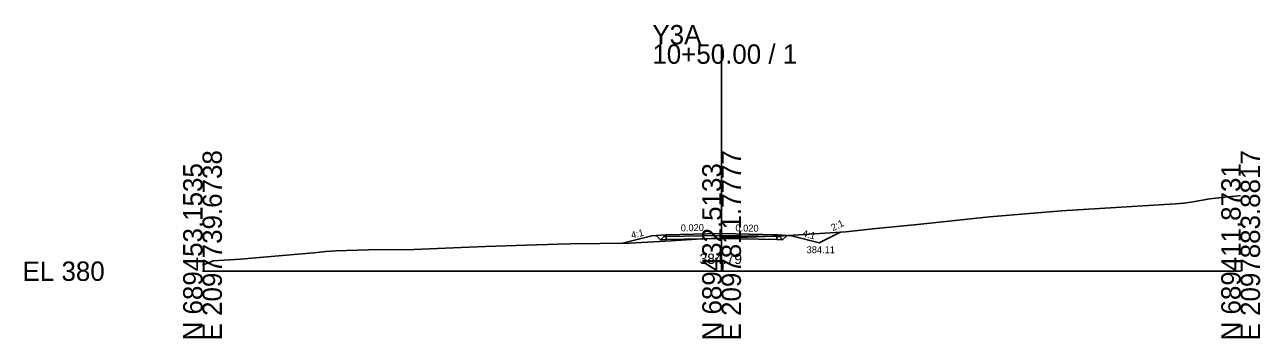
# Model space of a CAD drawing. Extents: x -26 to 2453, y -10 to 1032.
# Drawn here: x -25.7 to 152.8, y 490.3 to 535.6 of the extents above; entities that cross this region are included whole.
import ezdxf

# ---------------------------------------------------------------- set-up
doc = ezdxf.new("R2010")
doc.units = 0
for name, color, linetype in [('Exist Cross Section Cell', 7, 'Continuous'), ('Exist XS Center Line Elevation Label', 7, 'Continuous'), ('Exist XS Ground Line', 7, 'Continuous'), ('Prop CMT Pvmt Course 1', 7, 'Continuous'), ('Prop CMT Pvmt Course 2', 7, 'Continuous'), ('Prop CMT Pvmt Course 3', 7, 'Continuous'), ('Prop CMT Pvmt Surface', 7, 'Continuous'), ('Prop CMT Pvmt Surface Shoulder', 7, 'Continuous'), ('Prop CMT Shld Paved Course 1', 7, 'Continuous'), ('Prop CMT Shld Paved Course 2', 7, 'Continuous'), ('Prop CMT Shld Paved Course 3', 7, 'Continuous'), ('Prop CMT Slope Grass', 7, 'Continuous'), ('Prop CMT Subgrade Earthwork', 7, 'Continuous'), ('Prop XS SE Text', 7, 'Continuous'), ('Prop XS Side Slope Text', 7, 'Continuous')]:
    doc.layers.add(name, color=color, linetype=linetype)

msp = doc.modelspace()

# ---------------------------------------------------------------- linework, layer by layer
at = {"layer": 'Exist Cross Section Cell'}
for p, q in [((75, 500), (75, 532.77)), ((0, 500), (75, 500)), ((75, 500), (150, 500))]:
    msp.add_line(p, q, dxfattribs=at)
at = {"layer": 'Exist XS Ground Line'}
msp.add_lwpolyline([(0, 500.87), (1.56, 501.49), (5.49, 501.73), (11.57, 502.25), (16.06, 502.66), (17.84, 502.83), (19.29, 502.93), (23.98, 503.07), (30.51, 503.12), (38.55, 503.47), (40.91, 503.55), (46.8, 503.77), (51.32, 503.9), (53.13, 503.94), (61.72, 504.07), (67.7, 504.41), (72.12, 504.7), (75, 504.79), (82.52, 505.05), (83.14, 505.08), (92.93, 505.69), (96.85, 506.1), (103.33, 506.73), (111.43, 507.62), (113.73, 507.86), (119.48, 508.35), (124.14, 508.73), (140.6, 509.73), (141.74, 509.81), (142.84, 509.99), (145.53, 510.44), (148.6, 510.78), (148.92, 510.81), (150, 510.92)], dxfattribs=at)
at = {"layer": 'Prop CMT Pvmt Course 1'}
for points in [[(75, 505.43), (67, 505.27)], [(67, 505.27), (67, 505.02)], [(75, 505.18), (75, 505.43)], [(75, 505.43), (83, 505.27)], [(75, 505.18), (75, 505.43)], [(75, 505.18), (75, 505.43)], [(83, 505.27), (83, 505.02)], [(67, 505.02), (75, 505.18)], [(83, 505.02), (75, 505.18)]]:
    msp.add_lwpolyline(points, dxfattribs=at)
msp.add_lwpolyline([(75, 505.18), (75, 505.31), (75, 505.31), (75, 505.18)], close=True, dxfattribs=at)
msp.add_lwpolyline([(75, 505.18), (75, 505.31), (75, 505.31), (75, 505.18)], close=True, dxfattribs=at)
msp.add_lwpolyline([(75, 505.18), (75, 505.31), (75, 505.31), (75, 505.18)], close=True, dxfattribs=at)
msp.add_lwpolyline([(75, 505.18), (75, 505.31), (75, 505.31), (75, 505.18)], close=True, dxfattribs=at)
at = {"layer": 'Prop CMT Pvmt Course 2'}
for points in [[(67, 505.02), (75, 505.18)], [(75, 505.18), (67, 505.02)], [(67, 505.02), (67, 504.69)], [(75, 504.85), (75, 505.18)], [(83, 505.02), (75, 505.18)], [(75, 504.85), (75, 505.18)], [(75, 505.18), (83, 505.02)], [(75, 504.85), (75, 505.18)], [(83, 505.02), (83, 504.69)]]:
    msp.add_lwpolyline(points, dxfattribs=at)
at = {"layer": 'Prop CMT Pvmt Course 3'}
for points in [[(75, 505.18), (67, 505.02)], [(67, 505.02), (67, 504.56)], [(67, 504.56), (75, 504.72)], [(75, 505.18), (83, 505.02)], [(75, 504.72), (75, 505.18)], [(75, 504.72), (75, 505.18)], [(83, 504.56), (75, 504.72)], [(83, 505.02), (83, 504.56)]]:
    msp.add_lwpolyline(points, dxfattribs=at)
at = {"layer": 'Prop CMT Pvmt Surface'}
for points in [[(75, 505.43), (67, 505.27)], [(75, 505.43), (83, 505.27)]]:
    msp.add_lwpolyline(points, dxfattribs=at)
at = {"layer": 'Prop CMT Pvmt Surface Shoulder'}
for points in [[(67, 505.27), (66.9, 505.27)], [(83, 505.27), (83.1, 505.27)]]:
    msp.add_lwpolyline(points, dxfattribs=at)
at = {"layer": 'Prop CMT Shld Paved Course 1'}
for points in [[(67, 505.27), (66.9, 505.27), (66.64, 505.01)], [(67, 505.02), (67, 505.27)], [(83, 505.27), (83.1, 505.27), (83.36, 505.01)], [(83, 505.02), (83, 505.27)], [(66.64, 505.01), (67, 505.02)], [(83.36, 505.01), (83, 505.02)]]:
    msp.add_lwpolyline(points, dxfattribs=at)
at = {"layer": 'Prop CMT Shld Paved Course 2'}
for points in [[(67, 505.02), (66.64, 505.01), (66.31, 504.68)], [(66.64, 505.01), (67, 505.02)], [(67, 504.69), (67, 505.02)], [(83, 505.02), (83.36, 505.01), (83.69, 504.68)], [(83.36, 505.01), (83, 505.02)], [(83, 504.69), (83, 505.02)]]:
    msp.add_lwpolyline(points, dxfattribs=at)
at = {"layer": 'Prop CMT Shld Paved Course 3'}
for points in [[(66.64, 505.01), (66.18, 504.55)], [(66.18, 504.55), (67, 504.56)], [(66.31, 504.68), (66.31, 504.68)], [(67, 505.02), (66.64, 505.01)], [(67, 504.56), (67, 505.02)], [(83, 505.02), (83.36, 505.01)], [(83, 504.56), (83, 505.02)], [(83.82, 504.55), (83, 504.56)], [(83.36, 505.01), (83.82, 504.55)], [(83.69, 504.68), (83.69, 504.68)]]:
    msp.add_lwpolyline(points, dxfattribs=at)
at = {"layer": 'Prop CMT Slope Grass'}
for p, q in [((66.9, 505.27), (64.91, 505.11)), ((83.1, 505.27), (85.09, 505.11)), ((89.09, 504.11), (92.16, 505.64)), ((64.91, 505.11), (60.68, 504.05)), ((85.09, 505.11), (89.09, 504.11))]:
    msp.add_line(p, q, dxfattribs=at)
at = {"layer": 'Prop CMT Subgrade Earthwork'}
for points in [[(66.18, 504.55), (65.54, 505.16)], [(67, 504.56), (66.18, 504.55)], [(75, 504.72), (67, 504.56)], [(75, 504.72), (83, 504.56)], [(83, 504.56), (83.82, 504.55)], [(83.82, 504.55), (84.46, 505.16)]]:
    msp.add_lwpolyline(points, dxfattribs=at)

# ---------------------------------------------------------------- texts
at = {"layer": 'Exist Cross Section Cell'}
for s, p in [('Y3A', (65, 532.77)), ('10+50.00 / 1', (65, 529.97)), ('EL 380', (-26, 498.6))]:
    msp.add_text(s, height=2.8, dxfattribs=at).set_placement(p)
for s, p in [('E 2097739.6738', (2.8, 490)), ('E 2097811.7777', (77.8, 490)), ('E 2097883.8817', (152.8, 490)), ('N 689453.1535', (0, 490)), ('N 689432.5133', (75, 490)), ('N 689411.8731', (150, 490))]:
    msp.add_text(s, height=2.8, rotation=90, dxfattribs=at).set_placement(p)
at = {"layer": 'Exist XS Center Line Elevation Label'}
msp.add_text('384.79', height=1.5, dxfattribs=at).set_placement((71.81, 501.04))
at = {"layer": 'Prop XS SE Text'}
for rotation, p in [(1.1458, (69.11, 505.75)), (358.8542, (76.99, 505.76))]:
    msp.add_text('0.020', height=1, rotation=rotation, dxfattribs=at).set_placement(p)
msp.add_text('384.11', height=1, dxfattribs=at).set_placement((87.29, 502.6))
at = {"layer": 'Prop XS Side Slope Text'}
for s, rotation, p in [('2:1', 26.5651, (91.12, 505.77)), ('4:1', 14.0362, (62.04, 504.69)), ('4:1', 345.9638, (86.6, 505.04))]:
    msp.add_text(s, height=1, rotation=rotation, dxfattribs=at).set_placement(p)

doc.saveas('drawing.dxf')
